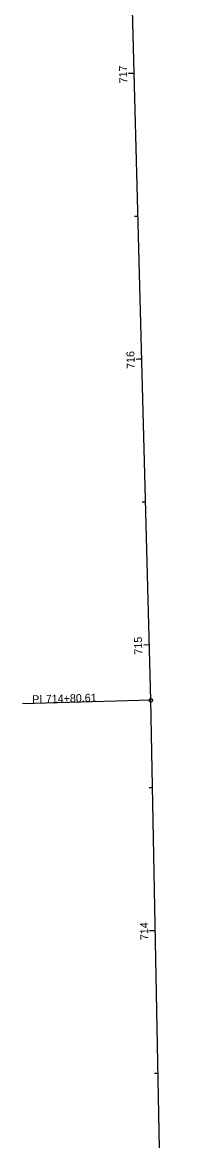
# Model space of a CAD drawing. Extents: x 2045805 to 2050091, y 455249 to 458900.
# Drawn here: x 2047568.4 to 2047631.2, y 457760.7 to 458151.9 of the extents above; entities that cross this region are included whole.
import ezdxf

# ---------------------------------------------------------------- set-up
doc = ezdxf.new("R2010")
doc.units = 0
for name, color, linetype in [('GE_P_Alignment_100_Bearings', 7, 'Continuous'), ('GE_P_Alignment_100_Cardinal_Points', 7, 'Continuous'), ('GE_P_Alignment_100_Distances', 7, 'Continuous'), ('GE_P_Alignment_100_Stations', 7, 'Continuous'), ('PF_P_Grade_Line', 7, 'Continuous'), ('PV_P_EOP', 7, 'Continuous'), ('PV_X_EOP', 7, 'Continuous')]:
    doc.layers.add(name, color=color, linetype=linetype)

msp = doc.modelspace()

# ---------------------------------------------------------------- linework, layer by layer
at = {"layer": 'GE_P_Alignment_100_Bearings'}
msp.add_line((2047613.37, 457914.72), (2047568.39, 457913.53), dxfattribs=at)
msp.add_circle((2047613.37, 457914.72), 0.6, dxfattribs=at)
at = {"layer": 'GE_P_Alignment_100_Cardinal_Points'}
for p, q in [((2047607.56, 458134.03), (2047605.57, 458133.98)), ((2047608.89, 458084.05), (2047607.69, 458084.02)), ((2047610.21, 458034.07), (2047608.21, 458034.01)), ((2047611.54, 457984.09), (2047610.34, 457984.05)), ((2047612.86, 457934.1), (2047610.86, 457934.05)), ((2047613.96, 457884.12), (2047612.76, 457884.09)), ((2047614.93, 457834.12), (2047612.93, 457834.09)), ((2047615.9, 457784.13), (2047614.7, 457784.11))]:
    msp.add_line(p, q, dxfattribs=at)
at = {"layer": 'GE_P_Alignment_100_Distances'}
msp.add_line((2047613.37, 457914.72), (2047568.39, 457913.53), dxfattribs=at)
msp.add_circle((2047613.37, 457914.72), 0.6, dxfattribs=at)
at = {"layer": 'GE_P_Alignment_100_Stations'}
for p, q in [((2047607.56, 458134.03), (2047606.37, 458134)), ((2047610.21, 458034.07), (2047609.01, 458034.04)), ((2047612.86, 457934.1), (2047610.86, 457934.05)), ((2047614.93, 457834.12), (2047613.73, 457834.1))]:
    msp.add_line(p, q, dxfattribs=at)
at = {"layer": 'PF_P_Grade_Line'}
msp.add_line((2047613.37, 457914.72), (2047568.39, 457913.53), dxfattribs=at)
msp.add_circle((2047613.37, 457914.72), 0.6, dxfattribs=at)
at = {"layer": 'PV_P_EOP'}
for p, q in [((2047613.37, 457914.72), (2047587.33, 458898)), ((2047631.15, 456996.2), (2047613.37, 457914.72))]:
    msp.add_line(p, q, dxfattribs=at)
at = {"layer": 'PV_X_EOP'}
msp.add_line((2047612.86, 457934.1), (2047611.66, 457934.07), dxfattribs=at)

# ---------------------------------------------------------------- texts
at = {"layer": 'GE_P_Alignment_100_Bearings'}
for s, p in [('PI', (2047571.85, 457913.67)), ('714+80.61', (2047576.63, 457913.8))]:
    msp.add_text(s, height=2.8, rotation=1.5169, dxfattribs=at).set_placement(p)
at = {"layer": 'GE_P_Alignment_100_Cardinal_Points'}
for s, rotation, p in [('717', 91.5169, (2047605.15, 458130.63)), ('716', 91.5169, (2047607.75, 458030.72)), ('715', 91.5169, (2047610.4, 457930.74)), ('714', 91.1089, (2047612.5, 457830.84))]:
    msp.add_text(s, height=2.8, rotation=rotation, dxfattribs=at).set_placement(p)
at = {"layer": 'GE_P_Alignment_100_Distances'}
for s, p in [('PI', (2047571.85, 457913.67)), ('714+80.61', (2047576.63, 457913.8))]:
    msp.add_text(s, height=2.8, rotation=1.5169, dxfattribs=at).set_placement(p)
at = {"layer": 'GE_P_Alignment_100_Stations'}
msp.add_text('715', height=2.8, rotation=91.5169, dxfattribs=at).set_placement((2047610.4, 457930.74))
at = {"layer": 'PF_P_Grade_Line'}
for s, p in [('PI', (2047571.85, 457913.67)), ('714+80.61', (2047576.63, 457913.8))]:
    msp.add_text(s, height=2.8, rotation=1.5169, dxfattribs=at).set_placement(p)

doc.saveas('drawing.dxf')
